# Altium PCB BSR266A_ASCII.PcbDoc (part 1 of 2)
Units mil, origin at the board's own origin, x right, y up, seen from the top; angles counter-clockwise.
Board outline 1624.02 x 1771.65 mil, 4 copper layers (Top Layer, GND 01, GND 02, Bottom Layer), stack 60.4 mil thick; 39 components, 9 nets, 52 pads, 271 vias.
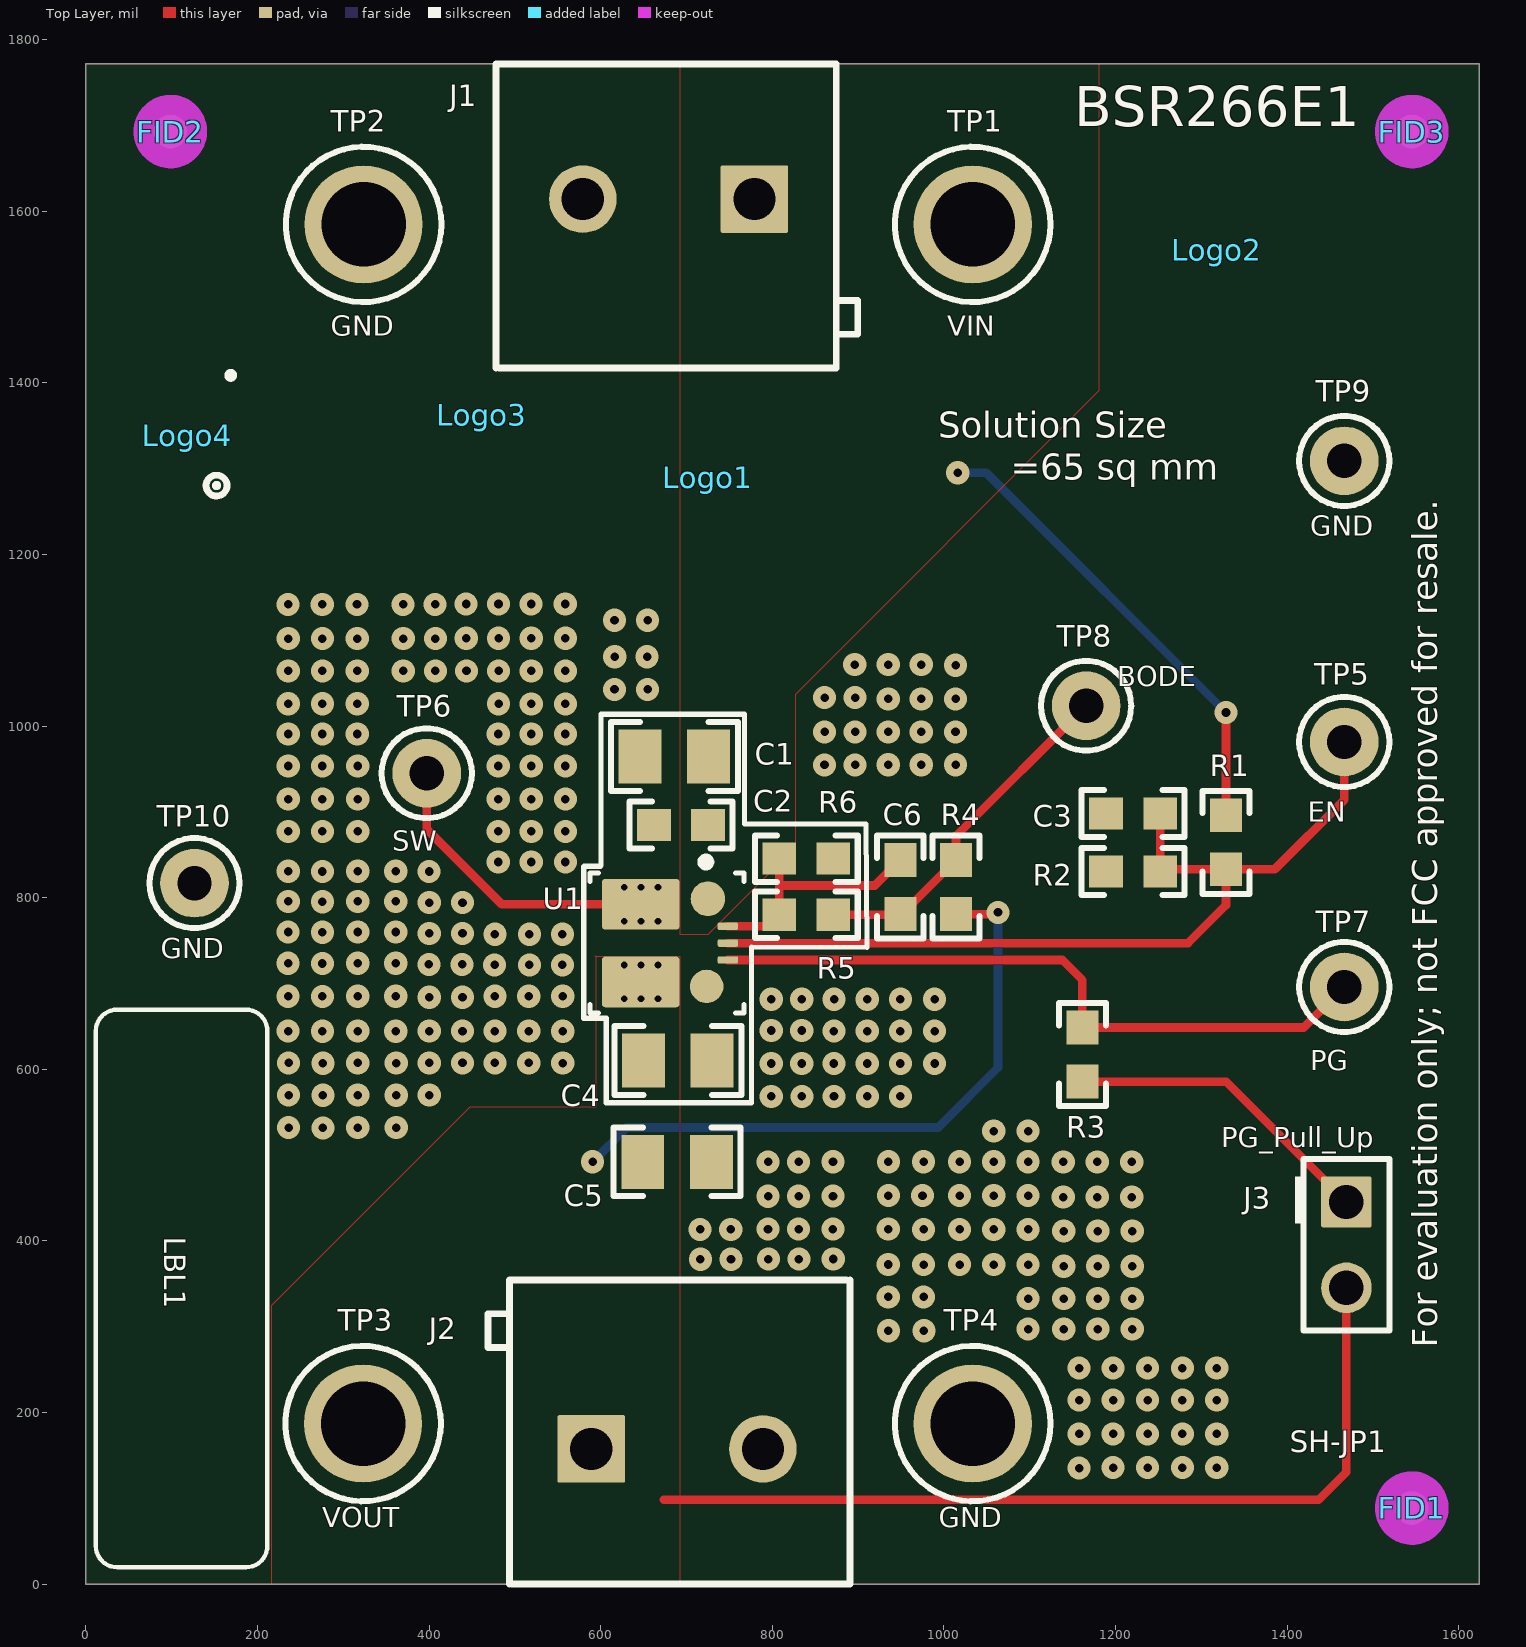
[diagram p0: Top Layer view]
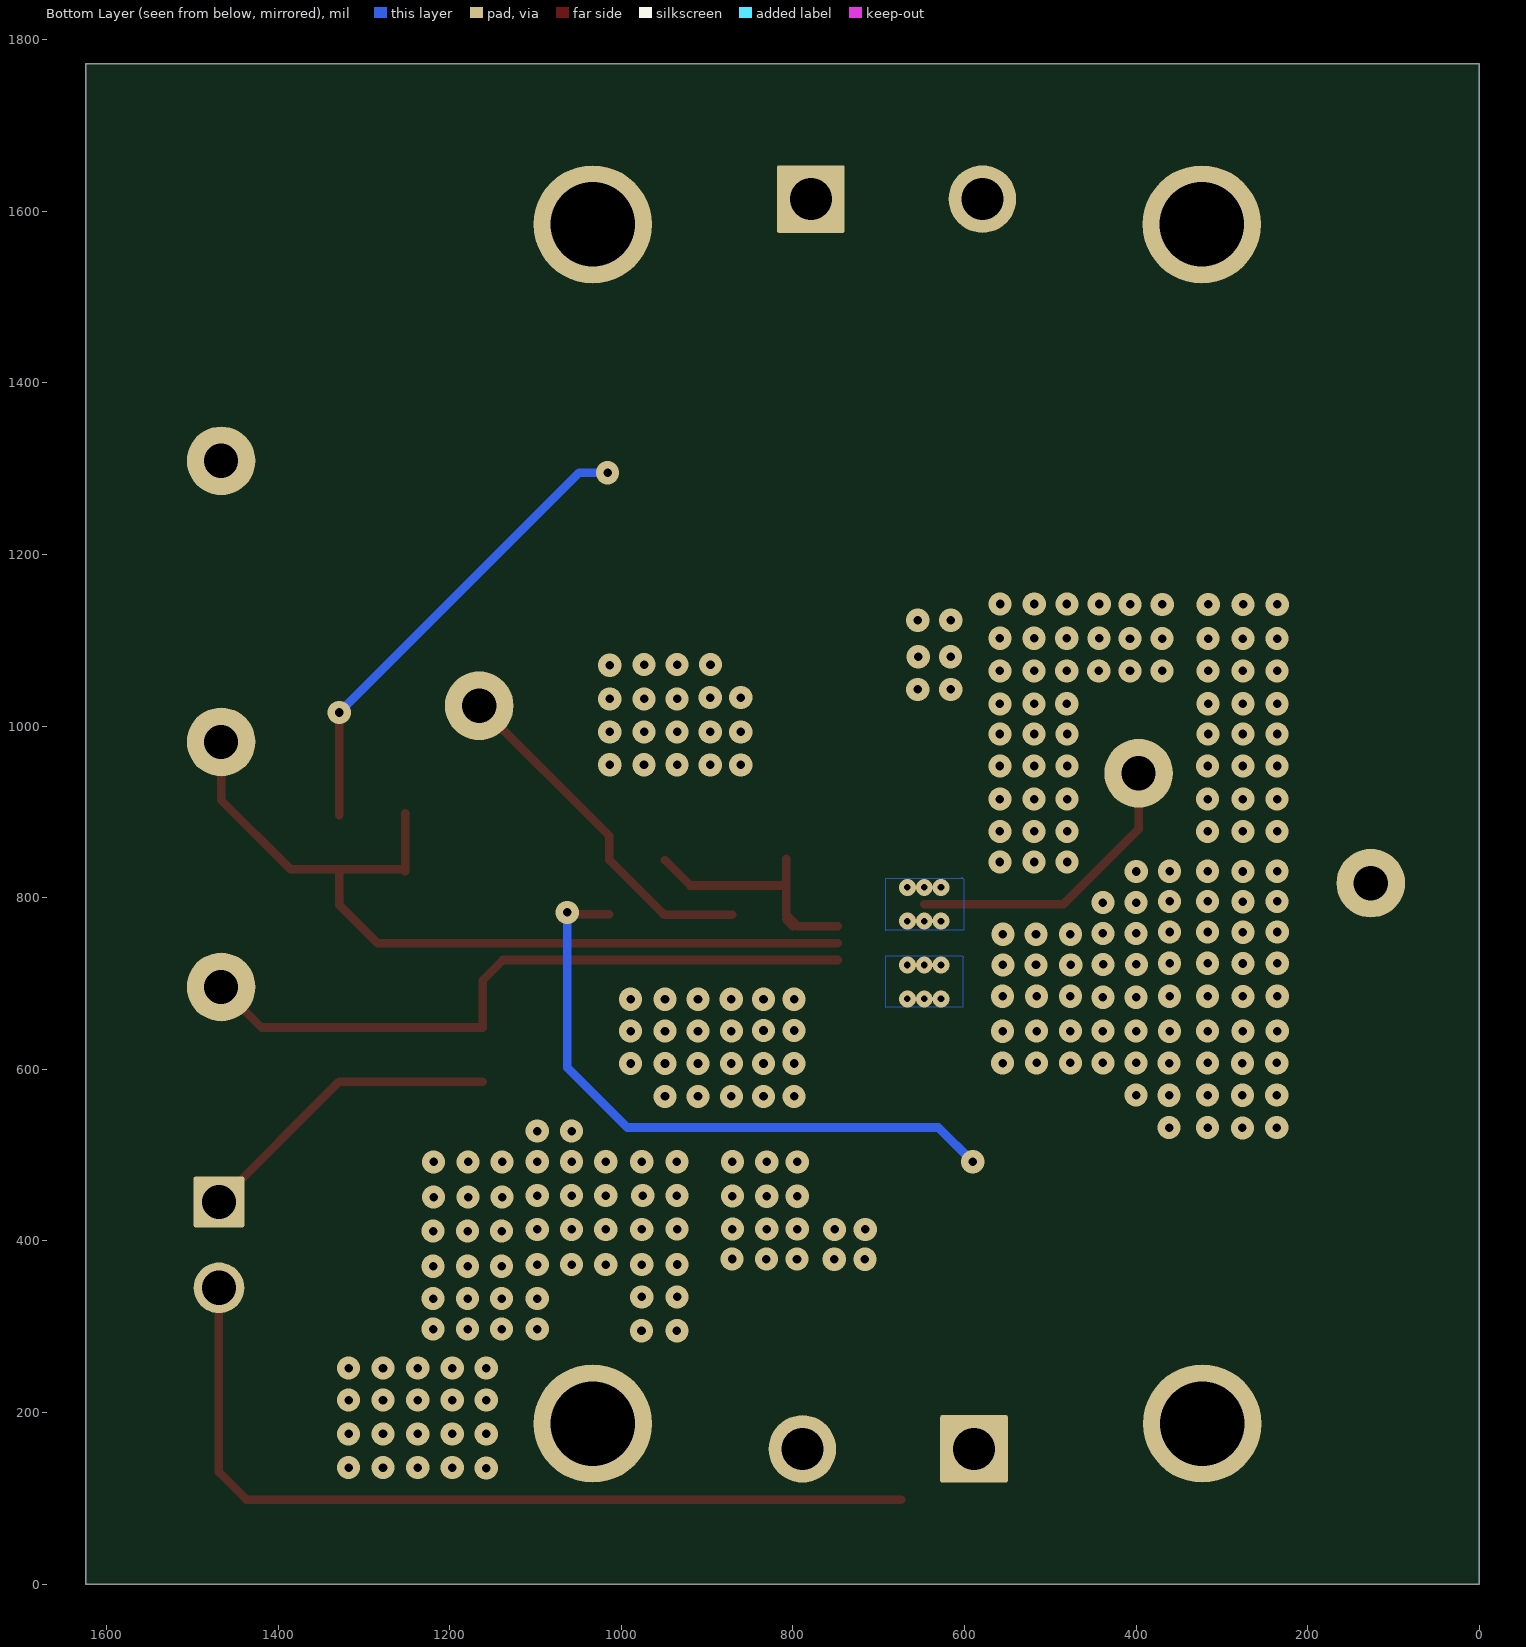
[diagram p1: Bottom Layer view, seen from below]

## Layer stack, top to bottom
Top Solder: solder mask 0.4, Solder Resist, Dk 3.5
Top Layer: signal copper 2.8
Dielectric 1: core 6, FR-4 High Tg, Dk 4.8
GND 01: signal copper 1.4
Dielectric 2: prepreg 40, FR-4 High Tg, Dk 4.8
GND 02: signal copper 1.4
Dielectric 3: core 6, FR-4 High Tg, Dk 4.2
Bottom Layer: signal copper 2.8
Bottom Solder: solder mask 0.4, Solder Resist, Dk 3.5

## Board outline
0,0 0,1771.65 1624.02,1771.65 1624.02,0

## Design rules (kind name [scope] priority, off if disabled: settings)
AcuteAngle [All] p0: scope1count=1 scope1_0_kind=Board scope1_0_value=Board scope2count=1 scope2_0_kind=Board scope2_0_value=Board commentlength=0 minimum=4.50000000000000E+0001
AcuteAngle [All] p1: minimum=4.50000000000000E+0001 checktracksonly=FALSE
AssemblyTestPointUsage [All] p0: scope1count=1 scope1_0_kind=Board scope1_0_value=Board scope2count=1 scope2_0_kind=Board scope2_0_value=Board commentlength=0
AssemblyTestPointUsage [All] p1: valid=2
AssemblyTestpoint [All] p0: scope1count=1 scope1_0_kind=Board scope1_0_value=Board scope2count=1 scope2_0_kind=Board scope2_0_value=Board commentlength=0
BoardOutlineClearance [All] p0 off: scope1count=1 scope1_0_kind=Board scope1_0_value=Board scope2count=1 scope2_0_kind=Board scope2_0_value=Board commentlength=172 gap=75 // Protel DXP Scope 1 Expression Was: OnCopper and Not InComponentClass('Logo') and not InComponentClass('FiducialMark') and not InRegion(1000,500,4000,800) and not InPoly
BoardOutlineClearance BoardOutlineClearance_Poly [All] p0 off: scope1count=1 scope1_0_kind=Board scope1_0_value=Board scope2count=1 scope2_0_kind=Board scope2_0_value=Board commentlength=58 gap=12 // Protel DXP Scope 1 Expression Was: OnCopper and IsPoly
BoardOutlineClearance BoardOutlineClearance_MountingHoles [All] p0 off: scope1count=1 scope1_0_kind=Board scope1_0_value=Board scope2count=1 scope2_0_kind=Board scope2_0_value=Board commentlength=86 gap=40 // Protel DXP Scope 1 Expression Was: OnCopper and InComponentClass('Mounting Holes')
BoardOutlineClearance BoardOutlineClearance_MountingHoles [OnCopper and InComponentClass('Mounting Holes')] p1: gap=40 ignorepadtopadclearanceinfootprint=FALSE
BoardOutlineClearance BoardOutlineClearance_Poly [OnCopper and IsPoly] p2: gap=12 ignorepadtopadclearanceinfootprint=FALSE
BoardOutlineClearance [OnCopper and Not InComponentClass('Logo') and not InComponentClass('FiducialMark') and not InRegion(1000,500,4000,800) and not InPoly] p3: gap=75 ignorepadtopadclearanceinfootprint=FALSE
Clearance [All] p0: scope1count=1 scope1_0_kind=Board scope1_0_value=Board scope2count=1 scope2_0_kind=Board scope2_0_value=Board commentlength=0 gap=5
Clearance Clearance_Poly [All] p0 off: scope1count=1 scope1_0_kind=Board scope1_0_value=Board scope2count=1 scope2_0_kind=Board scope2_0_value=Board commentlength=48 gap=8.5 // Protel DXP Scope 1 Expression Was: InPolygon
Clearance Clearance_Keepouts [All] p0 off: scope1count=1 scope1_0_kind=Board scope1_0_value=Board scope2count=1 scope2_0_kind=Board scope2_0_value=Board commentlength=99 gap=0 // Protel DXP Scope 2 Expression Was: ((IsTrack Or IsArc) And Not InPoly) And IsFree and IsKeepOut
Clearance Clearance_Keepouts [((IsTrack Or IsArc) And Not InPoly) And IsFree and IsKeepOut vs ((IsTrack Or IsArc) And Not InPoly) And IsFree and IsKeepOut] p1: gap=0 ignorepadtopadclearanceinfootprint=FALSE
Clearance Clearance_Poly [InPolygon] p2: gap=8.5 ignorepadtopadclearanceinfootprint=TRUE except(0: Arc-Hole Track-Hole SMDPad-Hole THPad-Hole Via-Hole Fill-Hole Poly-Hole Region-Hole Text-Hole)
Clearance [All] p3: gap=5 ignorepadtopadclearanceinfootprint=FALSE except(0: Arc-Hole Track-Hole SMDPad-Hole THPad-Hole Via-Hole Fill-Hole Poly-Hole Region-Hole Text-Hole)
ComponentClearance [All] p0: scope1count=1 scope1_0_kind=Board scope1_0_value=Board scope2count=1 scope2_0_kind=Board scope2_0_value=Board commentlength=0 gap=30 collisioncheckmode=3
ComponentClearance ComponentClearance_THtoTH [All] p0 off: scope1count=1 scope1_0_kind=Board scope1_0_value=Board scope2count=1 scope2_0_kind=Board scope2_0_value=Board commentlength=54 gap=30 collisioncheckmode=3 // Protel DXP Scope 2 Expression Was: IsThruComponent
ComponentClearance ComponentClearance_THtoSMT [All] p0 off: scope1count=1 scope1_0_kind=Board scope1_0_value=Board scope2count=1 scope2_0_kind=Board scope2_0_value=Board commentlength=53 gap=40 collisioncheckmode=3 // Protel DXP Scope 2 Expression Was: IsSMTComponent
ComponentClearance ComponentClearance_SmallPassives [All] p0 off: scope1count=1 scope1_0_kind=Board scope1_0_value=Board scope2count=1 scope2_0_kind=Board scope2_0_value=Board commentlength=508 gap=14.96 collisioncheckmode=3 // Protel DXP Scope 2 Expression Was: HasFootprint('0201*') or HasFootprint('0402*') or HasFootprint('0508') or HasFootprint('0603*') or HasFootprint('0612') or HasFootprint('0805*') or HasFootprint('0815*') or HasFootprint('0830*') or HasFootprint('1206*') or HasFootprint('1210*') or HasFootprint('1808*') or HasFootprint('1812*') or HasFootprint('1825*') or HasFootprint('2010*') or HasFootprint('2220*') or HasFootprint('2225*') or HasFootprint('2512*') or HasFootprint('2728*') or HasFootprint('3518*')
ComponentClearance ComponentClearance_MountingHoles [All] p0: scope1count=1 scope1_0_kind=ComponentClass scope1_0_value="Mounting Holes" scope2count=1 scope2_0_kind=Board scope2_0_value=Board commentlength=0 gap=250 collisioncheckmode=3
ComponentClearance ComponentClearance_ScrewToNut [All] p0 off: scope1count=1 scope1_0_kind=Board scope1_0_value=Board scope2count=1 scope2_0_kind=Board scope2_0_value=Board commentlength=71 gap=5 collisioncheckmode=3 // Protel DXP Scope 2 Expression Was: (HasFootprint('Keystone_1902C'))
ComponentClearance ComponentClearance_Logo [All] p0: scope1count=1 scope1_0_kind=ComponentClass scope1_0_value=Logo scope2count=1 scope2_0_kind=Board scope2_0_value=Board commentlength=0 gap=50 collisioncheckmode=3
ComponentClearance ComponentClearance_Shunt [All] p0: scope1count=1 scope1_0_kind=ComponentClass scope1_0_value=Header scope2count=1 scope2_0_kind=ComponentClass scope2_0_value=Shunt commentlength=0 gap=0 collisioncheckmode=3
ComponentClearance ComponentClearance_MountingHoles_FiducialMarks [All] p0: scope1count=1 scope1_0_kind=ComponentClass scope1_0_value="Mounting Holes" scope2count=1 scope2_0_kind=ComponentClass scope2_0_value=FiducialMark commentlength=0 gap=50 collisioncheckmode=3
ComponentClearance ComponentClearance_MountingHoles_FiducialMarks [InComponentClass('Mounting Holes') vs InComponentClass('FiducialMark')] p1: gap=50 collisioncheckmode=3 verticalgap=10 showdistances=FALSE
ComponentClearance ComponentClearance_Shunt [InComponentClass('Header') vs InComponentClass('Shunt')] p2: gap=0 collisioncheckmode=3 verticalgap=0 showdistances=FALSE
ComponentClearance ComponentClearance_Logo [InComponentClass('Logo')] p3: gap=50 collisioncheckmode=3 verticalgap=10 showdistances=FALSE
ComponentClearance ComponentClearance_ScrewToNut [(HasFootprint('NY PMS 440 0025 PH')) vs (HasFootprint('Keystone_1902C'))] p4: gap=5 collisioncheckmode=3 verticalgap=10 showdistances=FALSE
ComponentClearance ComponentClearance_MountingHoles [InComponentClass('Mounting Holes')] p5: gap=250 collisioncheckmode=3 verticalgap=100000 showdistances=FALSE
ComponentClearance ComponentClearance_SmallPassives [HasFootprint('0201*') or HasFootprint('0402*') or HasFootprint('0508') or HasFootprint('0603*') or HasFootprint('0612') or HasFootprint('0805*') or HasFootprint('0815*') or HasFootprint('0830*') or HasFootprint('1206*') or HasFootprint('1210*') or HasFootprint('1808*') or HasFootprint('1812*') or HasFootprint('1825*') or HasFootprint('2010*') or HasFootprint('2220*') or HasFootprint('2225*') or HasFootprint('2512*') or HasFootprint('2728*') or HasFootprint('3518*') vs HasFootprint('0201*') or HasFootprint('0402*') or HasFootprint('0508') or HasFootprint('0603*') or HasFootprint('0612') or HasFootprint('0805*') or HasFootprint('0815*') or HasFootprint('0830*') or HasFootprint('1206*') or HasFootprint('1210*') or HasFootprint('1808*') or HasFootprint('1812*') or HasFootprint('1825*') or HasFootprint('2010*') or HasFootprint('2220*') or HasFootprint('2225*') or HasFootprint('2512*') or HasFootprint('2728*') or HasFootprint('3518*')] p6: gap=14.96 collisioncheckmode=3 verticalgap=10 showdistances=FALSE
ComponentClearance ComponentClearance_THtoSMT [IsThruComponent vs IsSMTComponent] p7: gap=40 collisioncheckmode=3 verticalgap=30 showdistances=FALSE
ComponentClearance ComponentClearance_THtoTH [IsThruComponent vs IsThruComponent] p8: gap=30 collisioncheckmode=3 verticalgap=30 showdistances=FALSE
ComponentClearance [All] p9: gap=30 collisioncheckmode=3 verticalgap=10 showdistances=FALSE
DiffPairsRouting [All] p0: scope1count=1 scope1_0_kind=Board scope1_0_value=Board scope2count=1 scope2_0_kind=Board scope2_0_value=Board commentlength=0
DiffPairsRouting [All] p1: maxlimit=100 minlimit=10 mostfreqgap=10 toplayer_minwidth=15 toplayer_maxwidth=15 toplayer_prefwidth=15 midlayer1_minwidth=15 midlayer1_maxwidth=15 midlayer1_prefwidth=15 midlayer2_minwidth=15 midlayer2_maxwidth=15 midlayer2_prefwidth=15 bottomlayer_minwidth=15 bottomlayer_maxwidth=15 bottomlayer_prefwidth=15 maxuncoupledlength=1000
FabricationTestPointUsage TestPointUsage [All] p0: scope1count=1 scope1_0_kind=Board scope1_0_value=Board scope2count=1 scope2_0_kind=Board scope2_0_value=Board commentlength=0 valid=2 allowmultiple=FALSE
FabricationTestPointUsage TestPointUsage [All] p1: valid=2 allowmultiple=FALSE
FabricationTestpoint Testpoint [All] p0: scope1count=1 scope1_0_kind=Board scope1_0_value=Board scope2count=1 scope2_0_kind=Board scope2_0_value=Board commentlength=0 side=3 testpointundercomponent=TRUE minsize=40 maxsize=100 preferedsize=60 minholesize=0 maxholesize=40 preferedholesize=32 testpointgrid=1
FabricationTestpoint Testpoint [All] p1: side=3 testpointundercomponent=TRUE minsize=40 maxsize=100 preferedsize=60 minholesize=0 maxholesize=40 preferedholesize=32 testpointgrid=1 allowsidetop=TRUE allowsidebottom=TRUE usegrid=TRUE gridtolerance=0.01
FanoutControl Fanout_Small [All] p0 off: scope1count=1 scope1_0_kind=Board scope1_0_value=Board scope2count=1 scope2_0_kind=Board scope2_0_value=Board commentlength=84 // Protel DXP Scope 1 Expression Was: (CompPinCount < 5)   Fanout_Small (Default Rule)
FanoutControl Fanout_Default [All] p0: scope1count=1 scope1_0_kind=Board scope1_0_value=Board scope2count=1 scope2_0_kind=Board scope2_0_value=Board commentlength=30 // Fanout_Default (Default Rule)
FanoutControl Fanout_SOIC [All] p0 off: scope1count=1 scope1_0_kind=Board scope1_0_value=Board scope2count=1 scope2_0_kind=Board scope2_0_value=Board commentlength=71 // Protel DXP Scope 1 Expression Was: IsSOIC   Fanout_SOIC (Default Rule)
FanoutControl Fanout_BGA [All] p0 off: scope1count=1 scope1_0_kind=Board scope1_0_value=Board scope2count=1 scope2_0_kind=Board scope2_0_value=Board commentlength=69 // Protel DXP Scope 1 Expression Was: IsBGA   Fanout_BGA (Default Rule)
FanoutControl Fanout_LCC [All] p0 off: scope1count=1 scope1_0_kind=Board scope1_0_value=Board scope2count=1 scope2_0_kind=Board scope2_0_value=Board commentlength=69 // Protel DXP Scope 1 Expression Was: IsLCC   Fanout_LCC (Default Rule)
FanoutControl Fanout_LCC [IsLCC] p1: bgadir=Out bgaviamode=Centered fanoutstyle=Auto fanoutdirection=Alternating viagrid=1 // Fanout_LCC (Default Rule)
FanoutControl Fanout_BGA [IsBGA] p2: bgadir=Out bgaviamode=Centered fanoutstyle=Auto fanoutdirection=Alternating viagrid=1 // Fanout_BGA (Default Rule)
FanoutControl Fanout_Default [All] p4: bgadir=Out bgaviamode=Centered fanoutstyle=Auto fanoutdirection=Alternating viagrid=1 // Fanout_Default (Default Rule)
FanoutControl Fanout_Small [(CompPinCount < 5)] p5: bgadir=Out bgaviamode=Centered fanoutstyle=Auto fanoutdirection=OutThenIn viagrid=1 // Fanout_Small (Default Rule)
Height [All] p0: scope1count=1 scope1_0_kind=Board scope1_0_value=Board scope2count=1 scope2_0_kind=Board scope2_0_value=Board commentlength=0
HoleSize [All] p0: scope1count=1 scope1_0_kind=Board scope1_0_value=Board scope2count=1 scope2_0_kind=Board scope2_0_value=Board commentlength=0 absolutevalues=TRUE maxlimit=251 minlimit=7.87 maxpercent=80.000 minpercent=20.000
HoleSize [All] p1: absolutevalues=TRUE maxlimit=251 minlimit=7.87 maxpercent=80.000 minpercent=20.000
HoleToHoleClearance [All] p0: scope1count=1 scope1_0_kind=Board scope1_0_value=Board scope2count=1 scope2_0_kind=Board scope2_0_value=Board commentlength=0
LayerPairs [All] p0: scope1count=1 scope1_0_kind=Board scope1_0_value=Board scope2count=1 scope2_0_kind=Board scope2_0_value=Board commentlength=0 enforce=TRUE
MinimumAnnularRing [All] p0: scope1count=1 scope1_0_kind=Board scope1_0_value=Board scope2count=1 scope2_0_kind=Board scope2_0_value=Board commentlength=0 minimumring=6
MinimumAnnularRing MinimumAnnularRing_ThermalPadVias [All] p0 off: scope1count=1 scope1_0_kind=Board scope1_0_value=Board scope2count=1 scope2_0_kind=Board scope2_0_value=Board commentlength=63 minimumring=5.91 // Protel DXP Scope 1 Expression Was: IsVia and InAnyComponent
MinimumAnnularRing MinimumAnnularRing_ThermalPadVias [IsVia and InAnyComponent] p1: minimumring=5.91
MinimumAnnularRing [All] p2: minimumring=6
MinimumSolderMaskSliver [All] p0: scope1count=1 scope1_0_kind=Board scope1_0_value=Board scope2count=1 scope2_0_kind=Board scope2_0_value=Board commentlength=0
MinimumSolderMaskSliver MinimumSolderMaskSliver_Logo [All] p0: scope1count=1 scope1_0_kind=ComponentClass scope1_0_value=Logo scope2count=1 scope2_0_kind=ComponentClass scope2_0_value=Logo commentlength=0
MinimumSolderMaskSliver MinimumSolderMaskSliver_Logo [InComponentClass('Logo') vs InComponentClass('Logo')] p1: minsoldermaskwidth=0.7
MinimumSolderMaskSliver [All] p2: minsoldermaskwidth=3.94
NetAntennae [All] p0: scope1count=1 scope1_0_kind=Board scope1_0_value=Board scope2count=1 scope2_0_kind=Board scope2_0_value=Board commentlength=0
PasteMaskExpansion [All] p0: scope1count=1 scope1_0_kind=Board scope1_0_value=Board scope2count=1 scope2_0_kind=Board scope2_0_value=Board commentlength=0 expansion=0
PlaneClearance [All] p0: scope1count=1 scope1_0_kind=Board scope1_0_value=Board scope2count=1 scope2_0_kind=Board scope2_0_value=Board commentlength=0 clearance=0
PlaneClearance [All] p1: clearance=0
PlaneConnect [All] p0: scope1count=1 scope1_0_kind=Board scope1_0_value=Board scope2count=1 scope2_0_kind=Board scope2_0_value=Board commentlength=0 planeconnectstyle=Direct reliefexpansion=10 reliefentries=2 reliefconductorwidth=10 reliefairgap=10
PlaneConnect [All] p1: planeconnectstyle=Direct reliefexpansion=10 reliefentries=2 reliefconductorwidth=10 reliefairgap=10
PolygonConnect [All] p0: scope1count=1 scope1_0_kind=Board scope1_0_value=Board scope2count=1 scope2_0_kind=Board scope2_0_value=Board commentlength=0 connectstyle=Direct reliefconductorwidth=10 reliefentries=4 polygonreliefangle="90 Angle"
PolygonConnect [All] p1: connectstyle=Direct reliefconductorwidth=10 reliefentries=4 polygonreliefangle="90 Angle" airgapwidth=10
RoutingCorners [All] p0: scope1count=1 scope1_0_kind=Board scope1_0_value=Board scope2count=1 scope2_0_kind=Board scope2_0_value=Board commentlength=0 cornerstyle=45-Degree minsetback=100 maxsetback=100
RoutingLayers [All] p0: scope1count=1 scope1_0_kind=Board scope1_0_value=Board scope2count=1 scope2_0_kind=Board scope2_0_value=Board commentlength=0 top layer=Automatic mid layer 1=Automatic mid layer 2=Automatic bottom layer=Automatic
RoutingPriority [All] p0: scope1count=1 scope1_0_kind=Board scope1_0_value=Board scope2count=1 scope2_0_kind=Board scope2_0_value=Board commentlength=0
RoutingTopology [All] p0: scope1count=1 scope1_0_kind=Board scope1_0_value=Board scope2count=1 scope2_0_kind=Board scope2_0_value=Board commentlength=0 topology=Shortest
RoutingVias [All] p0: scope1count=1 scope1_0_kind=Board scope1_0_value=Board scope2count=1 scope2_0_kind=Board scope2_0_value=Board commentlength=0 holewidth=16 width=34 viastyle="Through Hole" minholewidth=7.87 minwidth=26 maxholewidth=40 maxwidth=65
RoutingVias ThermalPadVias [All] p0 off: scope1count=1 scope1_0_kind=Board scope1_0_value=Board scope2count=1 scope2_0_kind=Board scope2_0_value=Board commentlength=63 holewidth=7.87 width=19.68 viastyle="Through Hole" minholewidth=7.87 minwidth=19.68 maxholewidth=12.99 maxwidth=23.62 // Protel DXP Scope 1 Expression Was: IsVia and InAnyComponent
RoutingVias ThermalPadVias [IsVia and InAnyComponent] p1: holewidth=7.87 width=19.68 viastyle="Through Hole" minholewidth=7.87 minwidth=19.68 maxholewidth=12.99 maxwidth=23.62
RoutingVias [All] p2: holewidth=16 width=34 viastyle="Through Hole" minholewidth=7.87 minwidth=26 maxholewidth=40 maxwidth=65
ShortCircuit [All] p0: scope1count=1 scope1_0_kind=Board scope1_0_value=Board scope2count=1 scope2_0_kind=Board scope2_0_value=Board commentlength=0 allowed=FALSE
SilkToBoardRegionClearance [All] p0 off: scope1count=1 scope1_0_kind=Board scope1_0_value=Board scope2count=1 scope2_0_kind=Board scope2_0_value=Board commentlength=130 // Protel DXP Scope 1 Expression Was: Not ((IsComment or IsDesignator) And (Hide <> 'False')) and not InRegion(1000,500,4000,800)
SilkToBoardRegionClearance [Not ((IsComment or IsDesignator) And (Hide <> 'False')) and not InRegion(1000,500,4000,800)] p1:
SilkToSilkClearance [All] p0: scope1count=1 scope1_0_kind=Board scope1_0_value=Board scope2count=1 scope2_0_kind=Board scope2_0_value=Board commentlength=0
SilkToSilkClearance SilkToSilkClearance_Pb-FreeLogo [All] p0 off: scope1count=1 scope1_0_kind=Board scope1_0_value=Board scope2count=1 scope2_0_kind=Board scope2_0_value=Board commentlength=120 // Protel DXP Scope 2 Expression Was: (HasFootprint('Pb-Free_Overlay_Medium') OR HasFootprint('Pb-Free_Overlay_Small'))
SilkToSilkClearance SilkToSilkClearance_Pb-FreeLogo [(HasFootprint('Pb-Free_Overlay_Medium') OR HasFootprint('Pb-Free_Overlay_Small')) vs (HasFootprint('Pb-Free_Overlay_Medium') OR HasFootprint('Pb-Free_Overlay_Small'))] p1: silktosilkclearance=0
SilkToSilkClearance [All] p2: silktosilkclearance=4
SilkToSolderMaskClearance "Silk to Solder Mask Opening" [All] p0: scope1count=1 scope1_0_kind=Board scope1_0_value=Board scope2count=1 scope2_0_kind=Board scope2_0_value=Board commentlength=0
SilkToSolderMaskClearance SilkToComponentPadClearance [All] p0 off: scope1count=1 scope1_0_kind=Board scope1_0_value=Board scope2count=1 scope2_0_kind=Board scope2_0_value=Board commentlength=87 // Protel DXP Scope 1 Expression Was: (IsPad or IsFill or IsRegion) and InAnycomponent
SilkToSolderMaskClearance SilkToComponentPadClearance [(IsPad or IsFill or IsRegion) and InAnycomponent] p1: minsilkscreentomaskgap=2 clearancetoexposedcopper=TRUE
SilkToSolderMaskClearance "Silk to Solder Mask Opening" [All] p2: minsilkscreentomaskgap=0.5 clearancetoexposedcopper=FALSE
SolderMaskExpansion [All] p0: scope1count=1 scope1_0_kind=Board scope1_0_value=Board scope2count=1 scope2_0_kind=Board scope2_0_value=Board commentlength=0 expansion=1.85
SolderMaskExpansion [All] p1: expansion=1.85 istentingtop=FALSE
UnRoutedNet [All] p0: scope1count=1 scope1_0_kind=Board scope1_0_value=Board scope2count=1 scope2_0_kind=Board scope2_0_value=Board commentlength=0
UnpouredPolygon [All] p0: scope1count=1 scope1_0_kind=Board scope1_0_value=Board scope2count=1 scope2_0_kind=Board scope2_0_value=Board commentlength=0
Width [All] p0: scope1count=1 scope1_0_kind=Board scope1_0_value=Board scope2count=1 scope2_0_kind=Board scope2_0_value=Board commentlength=0 maxlimit=100 minlimit=3 preferedwidth=10
Width [All] p1: maxlimit=100 minlimit=3 preferedwidth=10 midlayer1_minwidth=6 midlayer2_minwidth=6 bottomlayer_minwidth=6 minimp=50.000000 maximp=50.000000 favimp=50.000000 checkconnectedcopper=TRUE
14 further rules are at their usual default settings.

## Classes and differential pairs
component class Shunt: SH-JP1
component class Header: J3
component class BSR266A_Sch: C1 C2 C3 C4 C5 C6 J1 J2 J3 R1 R2 R3 R4 R5 R6 TP1 TP2 TP3 TP4 TP5 TP6 TP7 TP8 TP9 TP10 U1
component class Logo: Logo1
component class BSR266A_Hardware: FID1 FID2 FID3 LBL1 Logo1 Logo2 Logo3 Logo4 SH-JP1 ZZ1 ZZ2 ZZ3 ZZ4
component class FiducialMark: FID1 FID2 FID3
component class AssemblyNote: ZZ1 ZZ2 ZZ3 ZZ4
component class Label: LBL1

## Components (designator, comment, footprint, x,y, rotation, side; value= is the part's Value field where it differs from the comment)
C1 "GRM21BR61E106MA73L" 0805_HV 685.69,964.57 r180 top
C2 "C0603C104K5RACTU" 0603 693.62,884.82 r180 top
C3 "C0603X103K5RACTU" 0603 1220.47,898.2 r180 top
C4 "GRM21BC81C226ME44L" 0805_HV 689.81,610.24 r0 top
C5 "GRM21BC81C226ME44L" 0805_HV 688.98,492.13 r0 top
C6 "GRM1885C2A330JA01D" 0603 949.12,812.32 r90 top
FID1 "Fiducial" Fiducial10-20 1545.28,88.58 r0 top
FID2 "Fiducial" Fiducial10-20 98.43,1692.91 r0 top
FID3 "Fiducial" Fiducial10-20 1545.28,1692.91 r0 top
J1 "ED120/2DS" On-Shore_ED120_2DS 679.13,1614.17 r180 top
J2 "ED120/2DS" On-Shore_ED120_2DS 688.98,157.48 r0 top
J3 "PEC02SAAN" CONN_PEC02SAAN 1469.04,395.27 r270 top
LBL1 "THT-14-423-10" Label_650x200 111.45,344.49 r270 top
Logo1 "Texas Instruments" TI_Stacked_Overlay_Small 724.9,1289.37 r0 top
Logo2 "CE Mark" CE_Mark_5mm 1317.96,1554.88 r0 top
Logo3 "FCC disclaimer" FCC_disclaimer 461.17,1363.06 r0 top
Logo4 "WEEE logo" WEEE_Minimum 118.11,1338.58 r0 top
R1 "CRCW060362K0JNEA" 0603 1328.68,864.5 r90 top
R2 "CRCW060330K0JNEA" 0603 1220.47,830.56 r0 top
R3 "CRCW060310K0FKEA" 0603 1161.42,617.12 r270 top
R4 "CRCW060351R0JNEA" 0603 1014,812.32 r270 top
R5 "CRCW06037K50FKEA" 0603 839.54,780.09 r0 top
R6 "CRCW060310K0FKEA" 0603 839.54,845.47 r180 top
SH-JP1 "SNT-100-BK-G" SNT-100-BK-G 1469.04,295.29 r90 top
TP1 "1502-2" Keystone1502-2 1033.46,1584.65 r0 top
TP2 "1502-2" Keystone1502-2 323.57,1584.65 r0 top
TP3 "1502-2" Keystone1502-2 322.97,187.01 r0 top
TP4 "1502-2" Keystone1502-2 1033.46,187.01 r0 top
TP5 "5000" Keystone5000 1466.54,981.48 r90 top
TP6 "5000" Keystone5000 397.19,945 r90 top
TP7 "5000" Keystone5000 1466.54,695.86 r90 top
TP8 "5000" Keystone5000 1165.78,1023.62 r90 top
TP9 "5001" Keystone5001 1466.54,1309.05 r90 top
TP10 "5001" Keystone5001 126.5,816.93 r90 top
U1 "TPSM863252RDX" RDX0007A-MFG 673.23,747.03 r270 top
ZZ1 "This Assembly Note is for PCB labels only" AssemblyNoteLabel 1918.6,2707.68 r0 top locked
ZZ2 "These assemblies are ESD sensitive, ESD precautions shall be observed." AssemblyNote 1918.6,2598.8 r0 top locked
ZZ3 "These assemblies must be clean and free from flux and all contaminants. Use of no clean flux is not acceptable." AssemblyNote 1918.6,2510.24 r0 top locked
ZZ4 "These assemblies must comply with workmanship standards IPC-A-610 Class 2, unless otherwise specified." AssemblyNote 1918.6,2421.69 r0 top locked

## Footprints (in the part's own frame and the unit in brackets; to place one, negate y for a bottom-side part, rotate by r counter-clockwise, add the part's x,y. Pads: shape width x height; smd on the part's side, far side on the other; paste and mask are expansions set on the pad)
0603 [mm] "0603 from SM-752 data"
  rect 1x0.95 smd: 1(-0.8,0) 2(0.8,0)
  silkscreen extent -1.52,-0.69 1.52,0.69
0805_HV [mil] "0805 with 30mil clearance between pads"
  rect 50x63 smd: 1(-40,0) 2(40,0)
  silkscreen extent -74,-40 74,40
AssemblyNote [mil] "Assembly Note"
AssemblyNoteLabel [mil] "Assembly Note for PCB Labels"
CE_Mark_5mm [mil] "Minimum text height for CE Mark"
CONN_PEC02SAAN [mm] "SULLINS"
  rrect7% 1.5x1.5 hole 1.016: 1(-1.27,0)
  round 1.5 hole 1.016: 2(1.27,0)
  silkscreen extent -2.54,-1.52 2.54,1.27
FCC_disclaimer [mil]
Fiducial10-20 [mm]
  round 1 smd mask+0: 1(0,0)
  Top Layer keep-out circle w1.178: c0,0 r0.5
Keystone1502-2 [mm] "Double Turret"
  round 3.5 hole 2.5: 1(0,0)
  silkscreen extent -2.3,-2.3 2.3,2.3
Keystone5000 [mil] "For Keystone 500x miniature loop terminals"
  round 80 hole 40: 1(0,0)
  silkscreen extent -52,-52 52,52
Keystone5001 [mil] "For Keystone 500x miniature loop terminals"
  round 80 hole 40: 1(0,0)
  silkscreen extent -52,-52 52,52
Label_650x200 [mil] "Thermal Transfer Label"
  round 1 on Mech13: 0(0,0)
  silkscreen extent -325,-100 325,100
On-Shore_ED120_2DS [mm] "ONSHORE"
  rrect5% 2x2 hole 1.25: 1(-2.54,0)
  round 2 hole 1.25: 2(2.54,0)
  silkscreen extent -5.6,-4 5.12,5
RDX0007A-MFG [mm]
  round 1.025 smd paste-1000 mask+0: 1(-1.312,1.312)
  rrect13% 1.5x2.3 smd paste-1000 mask+0: 2(-1.15,-0.675) 3(1.15,-0.675)
  round 0.991 smd paste-1000 mask+0: 4(1.281,1.276)
  rrect45% 0.22x0.6 smd paste+0 mask+0: 5(0.5,1.9) 6(0,1.9) 7(-0.5,1.9)
  silkscreen extent -2.52,-2.17 2.07,2.37
SNT-100-BK-G [mil] "Samtec STEP model"
  round 1 on Mech3: 0(0,0)
TI_Stacked_Overlay_Small [mil]
WEEE_Minimum [mil] "WEEElie bin"
  silkscreen extent 22,-71 54,74

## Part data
C1: library part CMP-0008303-3, "CAP, CERM, 10 uF, 25 V, +/- 20%, X5R, 0805"
C2: library part CMP-0006861-3, "CAP, CERM, 0.1 uF, 50 V, +/- 10%, X7R, 0603"
C3: library part CMP-0006978-1, "CAP, CERM, 0.01 uF, 50 V, +/- 10%, X7R, 0603"
C4 C5: library part CMP-0008269-1, "CAP, CERM, 22 uF, 16 V, +/- 20%, X6S, 0805"
C6: library part CMP-0007263-3, "CAP, CERM, 33 pF, 100 V, +/- 5%, C0G/NP0, 0603"
FID1 FID2 FID3: library part CMP-0077181-1, "Fiducial mark.  There is nothing to buy or mount."
J1 J2: library part CMP-0074910-1, "Terminal Block, 5.08 mm, 2x1, Brass, TH"
J3: library part CMP-0002337-1, "Header, 100mil, 2x1, Tin, TH"
LBL1: library part CMP-0003625-1, "Thermal Transfer Printable Labels, 0.650\" W x 0.200\" H - 10,000 per roll"
Logo1: library part CMP-0074838-1, "Texas Instrument Corporate Signature"
Logo2: library part CMP-0074844-1
Logo3: library part CMP-0074847-1, "FCC_disclaimer"
Logo4: library part CMP-0074769-1
R1: library part CMP-0025838-3, "RES, 62 k, 5%, 0.1 W, 0603"
R2: library part CMP-0025782-1, "RES, 30 k, 5%, 0.1 W, 0603"
R3 R6: library part CMP-0021998-2, "RES, 10.0 k, 1%, 0.1 W, 0603"
R4: library part CMP-0025825-2, "RES, 51, 5%, 0.1 W, 0603"
R5: library part CMP-0022601-1, "RES, 7.50 k, 1%, 0.1 W, 0603"
SH-JP1: library part CMP-0003623-1, "Shunt, 100mil, Gold plated, Black"
TP1 TP2 TP3 TP4: library part CMP-0055113-1, "Terminal, Turret, TH, Double"
TP5 TP6 TP7 TP8: library part CMP-0055137-1, "Test Point, Miniature, Red, TH"
TP9 TP10: library part CMP-0055138-1, "Test Point, Miniature, Black, TH"
U1: library part CMP-0097277-1, "3V to 16 V Input, 3-A Synchronous Step-Down Voltage Regulator Module, QFN-FCMOD7"
ZZ1: library part CMP-0003616-3
ZZ2: library part CMP-0077236-1
ZZ3: library part CMP-0077237-1
ZZ4: library part CMP-0077238-1

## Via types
v1: diameter 27, hole 10, Top Layer to Bottom Layer, 259 vias
v2: diameter 19.68, hole 7.87, Top Layer to Bottom Layer, 12 vias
